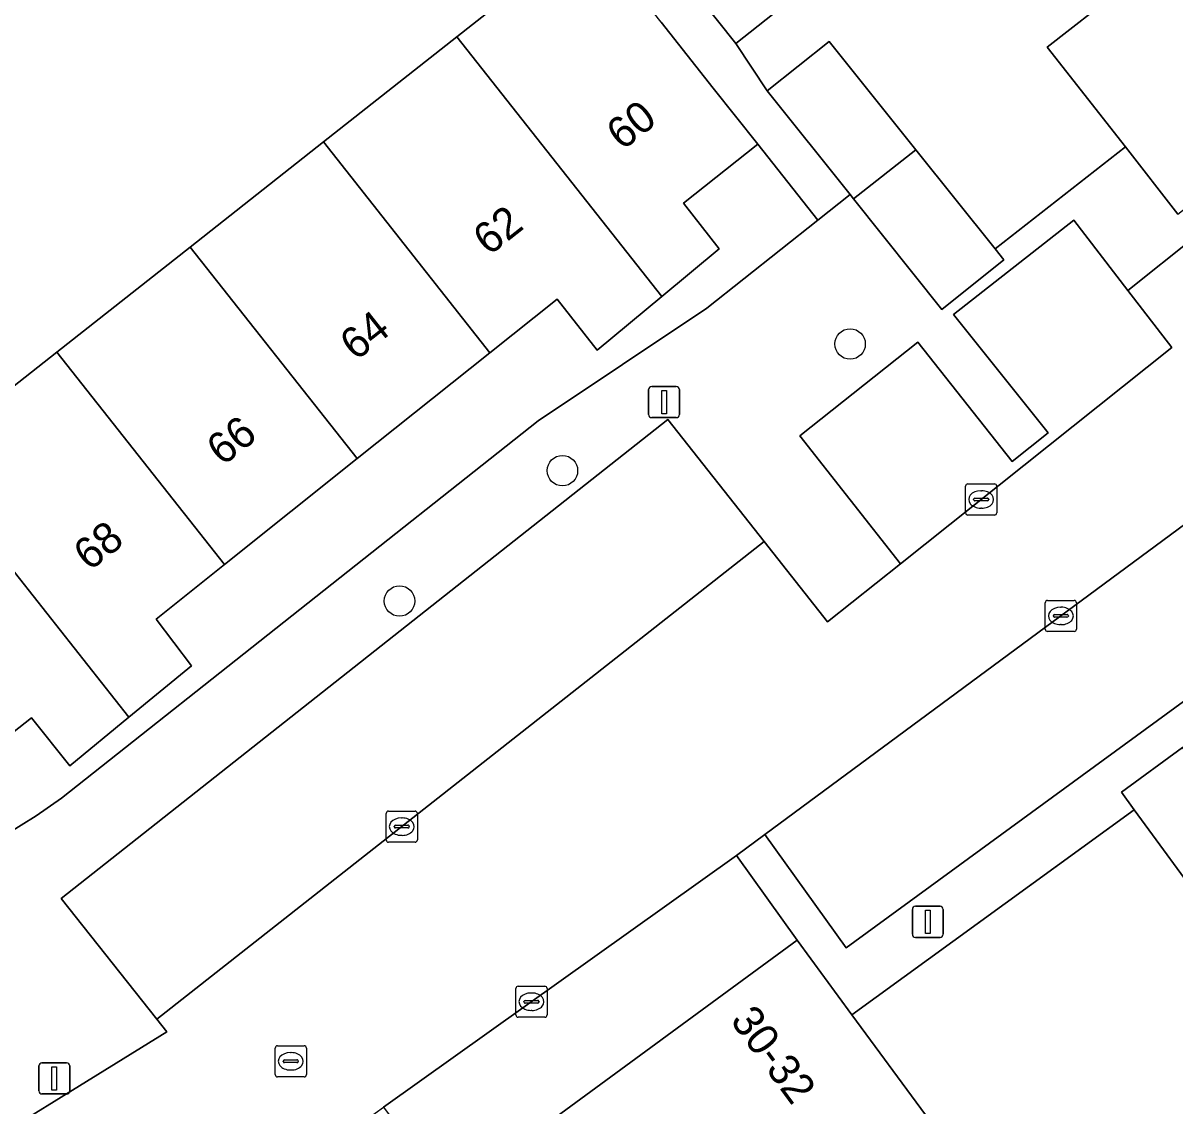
# Model space of a CAD drawing. Extents: x 160377 to 161131, y 383938 to 384853.
# Drawn here: x 160737.47 to 160774.47, y 384297.65 to 384332.45 of the extents above; entities that cross this region are included whole.
import ezdxf

# ---------------------------------------------------------------- set-up
doc = ezdxf.new("R2010")
doc.units = 0
for name, color, linetype in [('IMGEO_Boom', 7, 'Continuous'), ('IMGEO_Erf', 7, 'Continuous'), ('IMGEO_Kolk', 7, 'Continuous'), ('IMGEO_Lichtmast', 7, 'Continuous'), ('IMGEO_Muur', 7, 'Continuous'), ('IMGEO_Pand', 7, 'Continuous'), ('IMGEO_Pand_nummerreeks', 7, 'Continuous'), ('IMGEO_Parkeervlak_open', 7, 'Continuous'), ('IMGEO_Rijbaan_lokaal_open', 7, 'Continuous'), ('IMGEO_Rioolput', 7, 'Continuous'), ('IMGEO_Voetpad_open', 7, 'Continuous')]:
    doc.layers.add(name, color=color, linetype=linetype)

msp = doc.modelspace()

# ---------------------------------------------------------------- linework, layer by layer
at = {"layer": 'IMGEO_Boom'}
for centre in [(160764.034, 384322.134), (160754.794, 384318.064), (160749.562, 384313.876)]:
    msp.add_circle(centre, 0.489, dxfattribs=at)
at = {"layer": 'IMGEO_Erf'}
for points in [[(160755.67, 384335.373), (160749.349, 384343.365), (160747.381, 384341.823), (160744.281, 384345.742), (160741.198, 384343.303), (160741.57, 384342.833), (160738.089, 384340.068), (160734.536, 384337.245), (160732.947, 384339.237), (160731.553, 384338.11), (160733.127, 384336.126), (160729.549, 384333.283), (160726.08, 384330.527), (160724.514, 384332.494), (160723.697, 384331.842), (160725.266, 384329.88), (160721.037, 384326.521), (160728.057, 384317.554), (160732.347, 384320.938), (160734.275, 384318.494), (160738.556, 384321.872), (160742.837, 384325.249), (160747.119, 384328.627), (160751.4, 384332.004)], [(160754.02, 384319.665), (160759.431, 384323.288), (160763.003, 384326.115), (160761.067, 384328.549), (160758.683, 384326.653), (160759.824, 384325.188), (160757.988, 384323.659), (160755.914, 384321.931), (160754.622, 384323.569), (160752.467, 384321.851), (160748.204, 384318.451), (160743.94, 384315.051), (160741.742, 384313.298), (160742.881, 384311.796), (160740.868, 384310.142), (160738.969, 384308.582), (160737.742, 384310.124), (160735.391, 384308.28), (160734.223, 384309.758), (160732.288, 384312.201), (160735.06, 384308.02), (160736.437, 384306.072), (160737.893, 384306.973), (160738.707, 384307.538)], [(160749.048, 384297.616), (160753.569, 384291.536), (160756.007, 384293.325), (160753.616, 384296.583), (160762.333, 384302.98), (160760.382, 384305.698)]]:
    msp.add_lwpolyline(points, close=True, dxfattribs=at)
for points in [[(160762.515, 384333.499), (160760.359, 384331.787), (160761.367, 384330.263), (160763.358, 384331.856), (160766.149, 384328.367), (160768.692, 384325.189), (160772.875, 384328.466), (160770.365, 384331.67), (160772.644, 384333.455)], [(160781.693, 384295.545), (160779.177, 384298.972), (160781.143, 384300.415), (160780.127, 384301.799), (160778.161, 384300.357), (160775.484, 384304.001), (160773.157, 384307.171), (160764.092, 384300.584), (160766.451, 384297.369)]]:
    msp.add_lwpolyline(points, dxfattribs=at)
at = {"layer": 'IMGEO_Kolk'}
for p, q in [((160767.743, 384316.713), (160767.743, 384317.565)), ((160767.818, 384317.639), (160768.67, 384317.639)), ((160768.744, 384317.565), (160768.744, 384316.713)), ((160768.002, 384317.133), (160768.002, 384317.145)), ((160768.045, 384317.182), (160768.443, 384317.182)), ((160768.231, 384317.419), (160768.256, 384317.419)), ((160768.486, 384317.145), (160768.486, 384317.133)), ((160768.44, 384317.096), (160768.042, 384317.096)), ((160768.254, 384316.859), (160768.229, 384316.859)), ((160768.67, 384316.639), (160767.818, 384316.639)), ((160770.303, 384312.971), (160770.303, 384313.823)), ((160770.378, 384313.897), (160771.23, 384313.897)), ((160771.304, 384313.823), (160771.304, 384312.971)), ((160770.791, 384313.677), (160770.816, 384313.677)), ((160770.562, 384313.391), (160770.562, 384313.403)), ((160771, 384313.354), (160770.602, 384313.354)), ((160770.605, 384313.44), (160771.003, 384313.44)), ((160770.814, 384313.117), (160770.789, 384313.117)), ((160771.046, 384313.403), (160771.046, 384313.391)), ((160771.23, 384312.897), (160770.378, 384312.897)), ((160749.133, 384306.202), (160749.133, 384307.054)), ((160749.208, 384307.128), (160750.06, 384307.128)), ((160749.621, 384306.908), (160749.646, 384306.908)), ((160750.134, 384307.054), (160750.134, 384306.202)), ((160749.392, 384306.622), (160749.392, 384306.634)), ((160749.83, 384306.585), (160749.432, 384306.585)), ((160749.435, 384306.671), (160749.833, 384306.671)), ((160749.876, 384306.634), (160749.876, 384306.622)), ((160750.06, 384306.128), (160749.208, 384306.128)), ((160749.644, 384306.348), (160749.619, 384306.348)), ((160753.299, 384300.577), (160753.299, 384301.429)), ((160753.374, 384301.503), (160754.226, 384301.503)), ((160753.787, 384301.283), (160753.812, 384301.283)), ((160754.3, 384301.429), (160754.3, 384300.577)), ((160753.558, 384300.997), (160753.558, 384301.009)), ((160753.996, 384300.96), (160753.598, 384300.96)), ((160753.601, 384301.046), (160753.999, 384301.046)), ((160754.042, 384301.009), (160754.042, 384300.997)), ((160754.226, 384300.503), (160753.374, 384300.503)), ((160753.81, 384300.723), (160753.785, 384300.723))]:
    msp.add_line(p, q, dxfattribs=at)
for points in [[(160767.743, 384316.713), (160767.743, 384317.565)], [(160767.818, 384317.639), (160768.67, 384317.639)], [(160768.744, 384317.565), (160768.744, 384316.713)], [(160768.67, 384316.639), (160767.818, 384316.639)], [(160770.303, 384312.971), (160770.303, 384313.823)], [(160770.378, 384313.897), (160771.23, 384313.897)], [(160771.304, 384313.823), (160771.304, 384312.971)], [(160771.23, 384312.897), (160770.378, 384312.897)], [(160749.133, 384306.202), (160749.133, 384307.054)], [(160749.208, 384307.128), (160750.06, 384307.128)], [(160750.134, 384307.054), (160750.134, 384306.202)], [(160750.06, 384306.128), (160749.208, 384306.128)], [(160753.299, 384300.577), (160753.299, 384301.429)], [(160753.374, 384301.503), (160754.226, 384301.503)], [(160754.3, 384301.429), (160754.3, 384300.577)], [(160754.226, 384300.503), (160753.374, 384300.503)]]:
    msp.add_lwpolyline(points, dxfattribs=at)
for centre, radius, start, end in [((160767.82, 384317.563), 0.0765, 91.552, 178.448), ((160767.82, 384317.563), 0.0765, 91.552, 178.448), ((160768.668, 384317.563), 0.0765, 1.552, 88.448), ((160768.668, 384317.563), 0.0765, 1.552, 88.448), ((160768.042, 384317.142), 0.0403, 85.8775, 175.7526), ((160768.447, 384317.144), 0.0386, 1.7309, 96.639), ((160768.039, 384317.132), 0.0366, 178.938, 274.7102), ((160768.443, 384317.139), 0.043, 264.8664, 352.4533), ((160767.82, 384316.715), 0.0765, 181.552, 268.448), ((160767.82, 384316.715), 0.0765, 181.552, 268.448), ((160768.668, 384316.715), 0.0765, 271.552, 358.448), ((160768.668, 384316.715), 0.0765, 271.552, 358.448), ((160770.38, 384313.821), 0.0765, 91.552, 178.448), ((160770.38, 384313.821), 0.0765, 91.552, 178.448), ((160771.228, 384313.821), 0.0765, 1.552, 88.448), ((160771.228, 384313.821), 0.0765, 1.552, 88.448), ((160770.602, 384313.4), 0.0403, 85.8775, 175.7526), ((160770.599, 384313.39), 0.0366, 178.938, 274.7102), ((160771.003, 384313.397), 0.043, 264.8664, 352.4533), ((160771.007, 384313.402), 0.0386, 1.7309, 96.639), ((160770.38, 384312.973), 0.0765, 181.552, 268.448), ((160770.38, 384312.973), 0.0765, 181.552, 268.448), ((160771.228, 384312.973), 0.0765, 271.552, 358.448), ((160771.228, 384312.973), 0.0765, 271.552, 358.448), ((160749.21, 384307.052), 0.0765, 91.552, 178.448), ((160749.21, 384307.052), 0.0765, 91.552, 178.448), ((160750.058, 384307.052), 0.0765, 1.552, 88.448), ((160750.058, 384307.052), 0.0765, 1.552, 88.448), ((160749.432, 384306.631), 0.0403, 85.8775, 175.7526), ((160749.429, 384306.621), 0.0366, 178.938, 274.7102), ((160749.833, 384306.628), 0.043, 264.8664, 352.4533), ((160749.837, 384306.633), 0.0386, 1.7309, 96.639), ((160749.21, 384306.204), 0.0765, 181.552, 268.448), ((160749.21, 384306.204), 0.0765, 181.552, 268.448), ((160750.058, 384306.204), 0.0765, 271.552, 358.448), ((160750.058, 384306.204), 0.0765, 271.552, 358.448), ((160753.376, 384301.427), 0.0765, 91.552, 178.448), ((160753.376, 384301.427), 0.0765, 91.552, 178.448), ((160754.224, 384301.427), 0.0765, 1.552, 88.448), ((160754.224, 384301.427), 0.0765, 1.552, 88.448), ((160753.598, 384301.006), 0.0403, 85.8775, 175.7526), ((160753.595, 384300.996), 0.0366, 178.938, 274.7102), ((160753.999, 384301.003), 0.043, 264.8664, 352.4533), ((160754.003, 384301.008), 0.0386, 1.7309, 96.639), ((160753.376, 384300.579), 0.0765, 181.552, 268.448), ((160753.376, 384300.579), 0.0765, 181.552, 268.448), ((160754.224, 384300.579), 0.0765, 271.552, 358.448), ((160754.224, 384300.579), 0.0765, 271.552, 358.448)]:
    msp.add_arc(centre, radius, start, end, dxfattribs=at)
for centre, major_axis, ratio, start_param, end_param in [((160768.23, 384317.139), (-0.387, 0.002), 0.722429, 4.712389, 7.853982), ((160768.255, 384317.139), (-0.39, 0.002), 0.717154, 1.570796, 4.712389), ((160770.79, 384313.397), (-0.387, 0.002), 0.722429, 4.712389, 7.853982), ((160770.815, 384313.397), (-0.39, 0.002), 0.717154, 1.570796, 4.712389), ((160749.62, 384306.628), (-0.387, 0.002), 0.722429, 4.712389, 7.853982), ((160749.645, 384306.628), (-0.39, 0.002), 0.717154, 1.570796, 4.712389), ((160753.786, 384301.003), (-0.387, 0.002), 0.722429, 4.712389, 7.853982), ((160753.811, 384301.003), (-0.39, 0.002), 0.717154, 1.570796, 4.712389)]:
    msp.add_ellipse(centre, major_axis=major_axis, ratio=ratio, start_param=start_param, end_param=end_param, dxfattribs=at)
at = {"layer": 'IMGEO_Lichtmast'}
for p, q in [((160757.562, 384319.867), (160757.562, 384320.667)), ((160757.562, 384320.667), (160757.562, 384319.867)), ((160757.662, 384320.767), (160758.452, 384320.767)), ((160758.452, 384320.767), (160757.662, 384320.767)), ((160758.552, 384320.667), (160758.552, 384319.867)), ((160758.552, 384319.867), (160758.552, 384320.667)), ((160758.452, 384319.767), (160757.662, 384319.767)), ((160757.662, 384319.767), (160758.452, 384319.767)), ((160766.034, 384303.169), (160766.034, 384303.969)), ((160766.034, 384303.969), (160766.034, 384303.169)), ((160766.134, 384304.069), (160766.924, 384304.069)), ((160766.924, 384304.069), (160766.134, 384304.069)), ((160767.024, 384303.969), (160767.024, 384303.169)), ((160767.024, 384303.169), (160767.024, 384303.969)), ((160766.924, 384303.069), (160766.134, 384303.069)), ((160766.134, 384303.069), (160766.924, 384303.069)), ((160738.077, 384299.04), (160738.867, 384299.04)), ((160738.867, 384299.04), (160738.077, 384299.04)), ((160737.977, 384298.14), (160737.977, 384298.94)), ((160737.977, 384298.94), (160737.977, 384298.14)), ((160738.967, 384298.94), (160738.967, 384298.14)), ((160738.967, 384298.14), (160738.967, 384298.94)), ((160738.867, 384298.04), (160738.077, 384298.04)), ((160738.077, 384298.04), (160738.867, 384298.04))]:
    msp.add_line(p, q, dxfattribs=at)
for points in [[(160757.982, 384320.642), (160758.132, 384320.642), (160758.132, 384319.892), (160757.982, 384319.892), (160757.982, 384320.642)], [(160766.454, 384303.944), (160766.604, 384303.944), (160766.604, 384303.194), (160766.454, 384303.194), (160766.454, 384303.944)], [(160738.397, 384298.915), (160738.547, 384298.915), (160738.547, 384298.165), (160738.397, 384298.165), (160738.397, 384298.915)]]:
    msp.add_lwpolyline(points, dxfattribs=at)
for centre, start, end in [((160757.662, 384320.667), 90, 180), ((160757.662, 384320.667), 90, 180), ((160758.452, 384320.667), 0, 90), ((160758.452, 384320.667), 360, 90), ((160757.662, 384319.867), 180, 270), ((160757.662, 384319.867), 180, 270), ((160758.452, 384319.867), 270, 0), ((160758.452, 384319.867), 270, 0), ((160766.134, 384303.969), 90, 180), ((160766.134, 384303.969), 90, 180), ((160766.924, 384303.969), 0, 90), ((160766.924, 384303.969), 360, 90), ((160766.134, 384303.169), 180, 270), ((160766.134, 384303.169), 180, 270), ((160766.924, 384303.169), 270, 0), ((160766.924, 384303.169), 270, 0), ((160738.077, 384298.94), 90, 180), ((160738.077, 384298.94), 90, 180), ((160738.867, 384298.94), 0, 90), ((160738.867, 384298.94), 360, 90), ((160738.077, 384298.14), 180, 270), ((160738.077, 384298.14), 180, 270), ((160738.867, 384298.14), 270, 0), ((160738.867, 384298.14), 270, 0)]:
    msp.add_arc(centre, 0.1, start, end, dxfattribs=at)
at = {"layer": 'IMGEO_Muur'}
for points in [[(160768.692, 384325.189), (160772.875, 384328.466)], [(160764.092, 384300.584), (160773.042, 384307.087)]]:
    msp.add_lwpolyline(points, dxfattribs=at)
at = {"layer": 'IMGEO_Pand'}
for points in [[(160780.522, 384336.316), (160782.871, 384338.156), (160781.263, 384340.208), (160772.644, 384333.455), (160770.365, 384331.67), (160772.875, 384328.466), (160774.566, 384326.307), (160783.117, 384333.004)], [(160757.547, 384335.327), (160760.359, 384331.787), (160762.515, 384333.499), (160759.715, 384337.024)], [(160751.4, 384332.004), (160757.988, 384323.659), (160759.824, 384325.188), (160758.683, 384326.653), (160761.067, 384328.549), (160759.638, 384330.352), (160757.964, 384332.47), (160755.67, 384335.373)], [(160751.4, 384332.004), (160747.119, 384328.627), (160752.467, 384321.851), (160754.622, 384323.569), (160755.914, 384321.931), (160757.988, 384323.659)], [(160766.149, 384328.367), (160763.358, 384331.856), (160761.367, 384330.263), (160764.033, 384326.931), (160764.142, 384326.795)], [(160742.837, 384325.249), (160748.204, 384318.451), (160752.467, 384321.851), (160747.119, 384328.627)], [(160766.149, 384328.367), (160764.142, 384326.795), (160766.984, 384323.243), (160768.975, 384324.836), (160768.692, 384325.189)], [(160738.556, 384321.872), (160743.94, 384315.051), (160748.204, 384318.451), (160742.837, 384325.249)], [(160738.556, 384321.872), (160734.275, 384318.494), (160740.868, 384310.142), (160742.881, 384311.796), (160741.742, 384313.298), (160743.94, 384315.051)], [(160734.275, 384318.494), (160732.347, 384320.938), (160728.057, 384317.554), (160729.985, 384315.11), (160732.288, 384312.201), (160734.223, 384309.758), (160735.391, 384308.28), (160737.742, 384310.124), (160738.969, 384308.582), (160740.868, 384310.142)], [(160774.715, 384309.175), (160772.747, 384307.73), (160773.157, 384307.171), (160775.484, 384304.001), (160777.452, 384305.445)], [(160755.296, 384289.183), (160763.875, 384295.479), (160766.451, 384297.369), (160764.092, 384300.584), (160762.333, 384302.98), (160753.616, 384296.583), (160756.007, 384293.325), (160753.569, 384291.536)]]:
    msp.add_lwpolyline(points, close=True, dxfattribs=at)
at = {"layer": 'IMGEO_Parkeervlak_open'}
for points in [[(160772.957, 384323.85), (160771.217, 384326.114), (160767.358, 384323.085), (160770.393, 384319.275), (160769.24, 384318.36), (160766.209, 384322.193), (160762.421, 384319.186), (160765.649, 384315.071), (160774.371, 384322.018)], [(160761.275, 384315.785), (160758.184, 384319.708), (160738.69, 384304.323), (160741.768, 384300.44)], [(160761.293, 384306.371), (160763.903, 384302.735), (160781.485, 384315.578), (160779.821, 384317.833), (160779.604, 384317.657), (160778.583, 384319.147)]]:
    msp.add_lwpolyline(points, close=True, dxfattribs=at)
at = {"layer": 'IMGEO_Rijbaan_lokaal_open'}
for points in [[(160785.23, 384331.026), (160784.161, 384332.424), (160775.244, 384325.441), (160775.131, 384325.585), (160772.957, 384323.85), (160774.371, 384322.018), (160765.649, 384315.071), (160763.307, 384313.206), (160761.275, 384315.785), (160741.768, 384300.44), (160742.088, 384300.038), (160734.254, 384295.2)], [(160760.382, 384305.698), (160761.293, 384306.371), (160778.583, 384319.147), (160779.604, 384317.657), (160779.821, 384317.833), (160789.826, 384325.15), (160788.635, 384326.714), (160788.858, 384326.869), (160785.679, 384330.858)], [(160730.162, 384285.599), (160741.939, 384292.91), (160743.299, 384293.783), (160747.713, 384296.654), (160749.048, 384297.616), (160760.382, 384305.698)]]:
    msp.add_lwpolyline(points, dxfattribs=at)
at = {"layer": 'IMGEO_Rioolput'}
for p, q in [((160745.568, 384298.663), (160745.568, 384299.515)), ((160745.643, 384299.589), (160746.495, 384299.589)), ((160746.569, 384299.515), (160746.569, 384298.663)), ((160745.827, 384299.083), (160745.827, 384299.095)), ((160746.265, 384299.046), (160745.867, 384299.046)), ((160745.87, 384299.132), (160746.268, 384299.132)), ((160746.056, 384299.369), (160746.081, 384299.369)), ((160746.311, 384299.095), (160746.311, 384299.083)), ((160746.079, 384298.809), (160746.054, 384298.809)), ((160746.495, 384298.589), (160745.643, 384298.589))]:
    msp.add_line(p, q, dxfattribs=at)
for points in [[(160745.568, 384298.663), (160745.568, 384299.515)], [(160745.643, 384299.589), (160746.495, 384299.589)], [(160746.569, 384299.515), (160746.569, 384298.663)], [(160746.495, 384298.589), (160745.643, 384298.589)]]:
    msp.add_lwpolyline(points, dxfattribs=at)
for centre, radius, start, end in [((160745.645, 384299.513), 0.0765, 91.552, 178.448), ((160745.645, 384299.513), 0.0765, 91.552, 178.448), ((160746.493, 384299.513), 0.0765, 1.552, 88.448), ((160746.493, 384299.513), 0.0765, 1.552, 88.448), ((160745.867, 384299.092), 0.0403, 85.8775, 175.7526), ((160745.864, 384299.082), 0.0366, 178.938, 274.7102), ((160746.268, 384299.089), 0.043, 264.8664, 352.4533), ((160746.272, 384299.094), 0.0386, 1.7309, 96.639), ((160745.645, 384298.665), 0.0765, 181.552, 268.448), ((160745.645, 384298.665), 0.0765, 181.552, 268.448), ((160746.493, 384298.665), 0.0765, 271.552, 358.448), ((160746.493, 384298.665), 0.0765, 271.552, 358.448)]:
    msp.add_arc(centre, radius, start, end, dxfattribs=at)
for centre, major_axis, ratio, start_param, end_param in [((160746.055, 384299.089), (-0.387, 0.002), 0.722429, 4.712389, 7.853982), ((160746.08, 384299.089), (-0.39, 0.002), 0.717154, 1.570796, 4.712389)]:
    msp.add_ellipse(centre, major_axis=major_axis, ratio=ratio, start_param=start_param, end_param=end_param, dxfattribs=at)
at = {"layer": 'IMGEO_Voetpad_open'}
for points in [[(160757.964, 384332.47), (160759.638, 384330.352), (160761.067, 384328.549), (160763.003, 384326.115), (160764.033, 384326.931), (160761.367, 384330.263), (160760.359, 384331.787), (160757.547, 384335.327)], [(160774.566, 384326.307), (160772.875, 384328.466), (160768.692, 384325.189), (160768.975, 384324.836), (160766.984, 384323.243), (160764.142, 384326.795), (160764.033, 384326.931), (160763.003, 384326.115), (160759.431, 384323.288), (160754.02, 384319.665), (160738.707, 384307.538), (160737.893, 384306.973), (160736.437, 384306.072)], [(160734.254, 384295.2), (160742.088, 384300.038), (160741.768, 384300.44), (160738.69, 384304.323), (160758.184, 384319.708), (160761.275, 384315.785), (160763.307, 384313.206), (160765.649, 384315.071), (160762.421, 384319.186), (160766.209, 384322.193), (160769.24, 384318.36), (160770.393, 384319.275), (160767.358, 384323.085), (160771.217, 384326.114), (160772.957, 384323.85), (160775.131, 384325.585)]]:
    msp.add_lwpolyline(points, dxfattribs=at)
msp.add_lwpolyline([(160774.715, 384309.175), (160775.975, 384310.105), (160775.596, 384310.622), (160777.622, 384312.108), (160777.889, 384311.744), (160782.079, 384314.774), (160781.485, 384315.578), (160763.903, 384302.735), (160761.293, 384306.371), (160760.382, 384305.698), (160762.333, 384302.98), (160764.092, 384300.584), (160773.157, 384307.171), (160772.747, 384307.73)], close=True, dxfattribs=at)

# ---------------------------------------------------------------- texts
at = {"layer": 'IMGEO_Pand_nummerreeks'}
for s, rotation, p in [('60', 38.2881, (160756.72, 384328.328)), ('62', 38.2881, (160752.436, 384324.946)), ('64', 38.2881, (160748.159, 384321.57)), ('66', 38.2881, (160743.879, 384318.192)), ('68', 38.2881, (160739.603, 384314.815)), ('30-32', 306.2755, (160760.162, 384300.394))]:
    msp.add_text(s, height=1, rotation=rotation, dxfattribs=at).set_placement(p)

doc.saveas('drawing.dxf')
